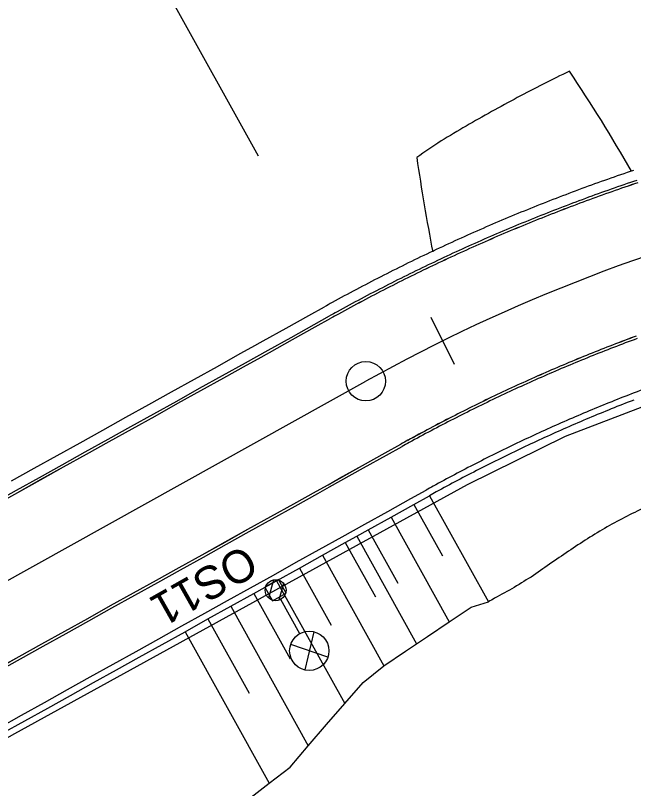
# Model space of a CAD drawing. Extents: x -783978 to -783565, y -1064821 to -1064596.
# Drawn here: x -783953.66 to -783930.06, y -1064761.44 to -1064731.94 of the extents above; entities that cross this region are included whole.
import ezdxf

# ---------------------------------------------------------------- set-up
doc = ezdxf.new("R2010")
doc.units = 0
doc.layers.add('SO 01_50_01', color=7, linetype='Continuous')
doc.layers.add('SO 01_86_02', color=7, linetype='Continuous')

msp = doc.modelspace()

# ---------------------------------------------------------------- linework, layer by layer
at = {"layer": 'SO 01_50_01'}
for p, q in [((-783958.827, -1064711.34), (-783944.395, -1064737.298)), ((-783942.455, -1064743.388), (-783941.862, -1064743.058)), ((-783942.455, -1064743.388), (-783941.862, -1064743.058)), ((-783942.455, -1064743.388), (-783941.862, -1064743.058)), ((-783943.329, -1064743.874), (-783942.455, -1064743.388)), ((-783943.329, -1064743.874), (-783942.455, -1064743.388)), ((-783943.329, -1064743.874), (-783942.455, -1064743.388)), ((-783942.261, -1064743.738), (-783941.668, -1064743.408)), ((-783942.213, -1064743.824), (-783941.619, -1064743.495)), ((-783942.212, -1064743.825), (-783941.619, -1064743.495)), ((-783936.899, -1064745.255), (-783937.783, -1064743.461)), ((-783944.203, -1064744.36), (-783943.329, -1064743.874)), ((-783944.203, -1064744.36), (-783943.329, -1064743.874)), ((-783944.203, -1064744.36), (-783943.329, -1064743.874)), ((-783943.135, -1064744.224), (-783942.261, -1064743.738)), ((-783943.087, -1064744.31), (-783942.213, -1064743.824)), ((-783943.086, -1064744.311), (-783942.212, -1064743.825)), ((-783944.009, -1064744.71), (-783943.135, -1064744.224)), ((-783944.64, -1064744.603), (-783944.203, -1064744.36)), ((-783944.64, -1064744.603), (-783944.203, -1064744.36)), ((-783944.64, -1064744.603), (-783944.203, -1064744.36)), ((-783943.961, -1064744.796), (-783943.087, -1064744.31)), ((-783943.96, -1064744.797), (-783943.086, -1064744.311)), ((-783945.951, -1064745.332), (-783945.077, -1064744.846)), ((-783945.951, -1064745.332), (-783945.077, -1064744.846)), ((-783945.951, -1064745.332), (-783945.077, -1064744.846)), ((-783945.077, -1064744.846), (-783944.64, -1064744.603)), ((-783945.077, -1064744.846), (-783944.64, -1064744.603)), ((-783945.077, -1064744.846), (-783944.64, -1064744.603)), ((-783944.446, -1064744.953), (-783944.009, -1064744.71)), ((-783944.398, -1064745.039), (-783943.961, -1064744.796)), ((-783944.397, -1064745.04), (-783943.96, -1064744.797)), ((-783944.883, -1064745.196), (-783944.446, -1064744.953)), ((-783944.835, -1064745.282), (-783944.398, -1064745.039)), ((-783944.834, -1064745.283), (-783944.397, -1064745.04)), ((-783946.825, -1064745.818), (-783945.951, -1064745.332)), ((-783946.825, -1064745.818), (-783945.951, -1064745.332)), ((-783946.825, -1064745.818), (-783945.951, -1064745.332)), ((-783945.757, -1064745.682), (-783944.883, -1064745.196)), ((-783945.709, -1064745.768), (-783944.835, -1064745.282)), ((-783945.708, -1064745.769), (-783944.834, -1064745.283)), ((-783946.631, -1064746.167), (-783945.757, -1064745.682)), ((-783972.341, -1064763.721), (-783940.283, -1064745.899)), ((-783947.699, -1064746.304), (-783946.825, -1064745.818)), ((-783947.699, -1064746.304), (-783946.825, -1064745.818)), ((-783947.699, -1064746.304), (-783946.825, -1064745.818)), ((-783946.583, -1064746.254), (-783945.709, -1064745.768)), ((-783946.582, -1064746.255), (-783945.708, -1064745.769)), ((-783948.573, -1064746.79), (-783947.699, -1064746.304)), ((-783948.573, -1064746.79), (-783947.699, -1064746.304)), ((-783948.573, -1064746.79), (-783947.699, -1064746.304)), ((-783947.505, -1064746.653), (-783946.631, -1064746.167)), ((-783947.457, -1064746.74), (-783946.583, -1064746.254)), ((-783947.457, -1064746.741), (-783946.582, -1064746.255)), ((-783949.447, -1064747.276), (-783948.573, -1064746.79)), ((-783949.447, -1064747.276), (-783948.573, -1064746.79)), ((-783949.447, -1064747.276), (-783948.573, -1064746.79)), ((-783948.379, -1064747.139), (-783947.505, -1064746.653)), ((-783948.331, -1064747.226), (-783947.457, -1064746.74)), ((-783948.331, -1064747.227), (-783947.457, -1064746.741)), ((-783949.253, -1064747.625), (-783948.379, -1064747.139)), ((-783950.321, -1064747.761), (-783949.447, -1064747.276)), ((-783950.321, -1064747.761), (-783949.447, -1064747.276)), ((-783950.321, -1064747.761), (-783949.447, -1064747.276)), ((-783949.205, -1064747.712), (-783948.331, -1064747.226)), ((-783949.205, -1064747.713), (-783948.331, -1064747.227)), ((-783951.196, -1064748.247), (-783950.321, -1064747.761)), ((-783951.196, -1064748.247), (-783950.321, -1064747.761)), ((-783951.196, -1064748.247), (-783950.321, -1064747.761)), ((-783950.127, -1064748.111), (-783949.253, -1064747.625)), ((-783950.079, -1064748.198), (-783949.205, -1064747.712)), ((-783950.079, -1064748.198), (-783949.205, -1064747.713)), ((-783952.07, -1064748.733), (-783951.196, -1064748.247)), ((-783952.07, -1064748.733), (-783951.196, -1064748.247)), ((-783952.07, -1064748.733), (-783951.196, -1064748.247)), ((-783951.001, -1064748.597), (-783950.127, -1064748.111)), ((-783950.953, -1064748.684), (-783950.079, -1064748.198)), ((-783950.953, -1064748.684), (-783950.079, -1064748.198)), ((-783939.54, -1064748.632), (-783938.947, -1064748.302)), ((-783939.539, -1064748.633), (-783938.946, -1064748.303)), ((-783939.491, -1064748.72), (-783938.898, -1064748.39)), ((-783951.875, -1064749.083), (-783951.001, -1064748.597)), ((-783951.827, -1064749.169), (-783950.953, -1064748.684)), ((-783951.827, -1064749.17), (-783950.953, -1064748.684)), ((-783940.414, -1064749.118), (-783939.54, -1064748.632)), ((-783940.413, -1064749.119), (-783939.539, -1064748.633)), ((-783952.944, -1064749.219), (-783952.07, -1064748.733)), ((-783952.944, -1064749.219), (-783952.07, -1064748.733)), ((-783952.944, -1064749.219), (-783952.07, -1064748.733)), ((-783940.365, -1064749.206), (-783939.491, -1064748.72)), ((-783953.818, -1064749.705), (-783952.944, -1064749.219)), ((-783953.818, -1064749.705), (-783952.944, -1064749.219)), ((-783953.818, -1064749.705), (-783952.944, -1064749.219)), ((-783952.749, -1064749.569), (-783951.875, -1064749.083)), ((-783952.701, -1064749.655), (-783951.827, -1064749.169)), ((-783952.701, -1064749.656), (-783951.827, -1064749.17)), ((-783941.288, -1064749.604), (-783940.414, -1064749.118)), ((-783941.287, -1064749.605), (-783940.413, -1064749.119)), ((-783941.239, -1064749.692), (-783940.365, -1064749.206)), ((-783953.623, -1064750.055), (-783952.749, -1064749.569)), ((-783953.575, -1064750.141), (-783952.701, -1064749.655)), ((-783953.575, -1064750.142), (-783952.701, -1064749.656)), ((-783942.162, -1064750.09), (-783941.725, -1064749.847)), ((-783942.162, -1064750.091), (-783941.725, -1064749.848)), ((-783941.725, -1064749.847), (-783941.288, -1064749.604)), ((-783941.725, -1064749.848), (-783941.287, -1064749.605)), ((-783941.676, -1064749.935), (-783941.239, -1064749.692)), ((-783954.497, -1064750.541), (-783953.623, -1064750.055)), ((-783954.449, -1064750.627), (-783953.575, -1064750.141)), ((-783954.449, -1064750.628), (-783953.575, -1064750.142)), ((-783943.036, -1064750.576), (-783942.162, -1064750.09)), ((-783943.036, -1064750.577), (-783942.162, -1064750.091)), ((-783942.113, -1064750.178), (-783941.676, -1064749.935)), ((-783938.568, -1064750.38), (-783937.975, -1064750.051)), ((-783942.987, -1064750.663), (-783942.113, -1064750.178)), ((-783939.442, -1064750.866), (-783938.568, -1064750.38)), ((-783938.447, -1064750.599), (-783937.853, -1064750.269)), ((-783938.447, -1064750.599), (-783937.853, -1064750.269)), ((-783938.447, -1064750.599), (-783937.853, -1064750.269)), ((-783937.853, -1064750.269), (-783935.603, -1064754.316)), ((-783943.91, -1064751.062), (-783943.036, -1064750.576)), ((-783943.91, -1064751.063), (-783943.036, -1064750.577)), ((-783943.861, -1064751.149), (-783942.987, -1064750.663)), ((-783939.321, -1064751.085), (-783938.447, -1064750.599)), ((-783939.321, -1064751.085), (-783938.447, -1064750.599)), ((-783939.321, -1064751.085), (-783938.447, -1064750.599)), ((-783938.447, -1064750.599), (-783937.356, -1064752.562)), ((-783940.316, -1064751.352), (-783939.442, -1064750.866)), ((-783944.784, -1064751.548), (-783943.91, -1064751.062)), ((-783944.784, -1064751.549), (-783943.91, -1064751.063)), ((-783944.735, -1064751.635), (-783943.861, -1064751.149)), ((-783940.753, -1064751.595), (-783940.316, -1064751.352)), ((-783940.195, -1064751.571), (-783939.321, -1064751.085)), ((-783940.195, -1064751.571), (-783939.321, -1064751.085)), ((-783940.195, -1064751.571), (-783939.321, -1064751.085)), ((-783939.321, -1064751.085), (-783937.097, -1064755.085)), ((-783945.658, -1064752.034), (-783944.784, -1064751.548)), ((-783945.658, -1064752.035), (-783944.784, -1064751.549)), ((-783945.609, -1064752.121), (-783944.735, -1064751.635)), ((-783941.19, -1064751.838), (-783940.753, -1064751.595)), ((-783940.632, -1064751.814), (-783940.195, -1064751.571)), ((-783940.632, -1064751.814), (-783940.195, -1064751.571)), ((-783940.632, -1064751.814), (-783940.195, -1064751.571)), ((-783940.195, -1064751.571), (-783939.062, -1064753.607)), ((-783942.064, -1064752.324), (-783941.19, -1064751.838)), ((-783941.069, -1064752.057), (-783940.632, -1064751.814)), ((-783941.069, -1064752.057), (-783940.632, -1064751.814)), ((-783941.069, -1064752.057), (-783940.632, -1064751.814)), ((-783940.632, -1064751.814), (-783938.347, -1064755.923)), ((-783946.532, -1064752.52), (-783945.658, -1064752.034)), ((-783946.532, -1064752.521), (-783945.658, -1064752.035)), ((-783946.483, -1064752.607), (-783945.609, -1064752.121)), ((-783941.943, -1064752.543), (-783941.069, -1064752.057)), ((-783941.943, -1064752.543), (-783941.069, -1064752.057)), ((-783941.943, -1064752.543), (-783941.069, -1064752.057)), ((-783941.069, -1064752.057), (-783939.917, -1064754.13)), ((-783947.406, -1064753.006), (-783946.532, -1064752.52)), ((-783947.406, -1064753.006), (-783946.532, -1064752.521)), ((-783942.938, -1064752.81), (-783942.064, -1064752.324)), ((-783947.357, -1064753.093), (-783946.483, -1064752.607)), ((-783943.812, -1064753.296), (-783942.938, -1064752.81)), ((-783942.817, -1064753.028), (-783941.943, -1064752.543)), ((-783942.817, -1064753.028), (-783941.943, -1064752.543)), ((-783942.817, -1064753.028), (-783941.943, -1064752.543)), ((-783941.943, -1064752.543), (-783939.597, -1064756.763)), ((-783948.28, -1064753.492), (-783947.406, -1064753.006)), ((-783948.28, -1064753.491), (-783947.406, -1064753.006)), ((-783948.231, -1064753.579), (-783947.357, -1064753.093)), ((-783943.691, -1064753.514), (-783942.817, -1064753.028)), ((-783943.691, -1064753.514), (-783942.817, -1064753.028)), ((-783943.691, -1064753.514), (-783942.817, -1064753.028)), ((-783942.817, -1064753.028), (-783941.602, -1064755.213)), ((-783944.686, -1064753.782), (-783943.812, -1064753.296)), ((-783949.154, -1064753.977), (-783948.28, -1064753.491)), ((-783949.154, -1064753.978), (-783948.28, -1064753.492)), ((-783949.106, -1064754.065), (-783948.231, -1064753.579)), ((-783944.565, -1064754), (-783943.691, -1064753.514)), ((-783944.565, -1064754), (-783943.691, -1064753.514)), ((-783944.565, -1064754), (-783943.691, -1064753.514)), ((-783943.691, -1064753.514), (-783941.088, -1064758.196)), ((-783950.028, -1064754.463), (-783949.154, -1064753.977)), ((-783950.028, -1064754.464), (-783949.154, -1064753.978)), ((-783945.56, -1064754.268), (-783944.686, -1064753.782)), ((-783945.439, -1064754.486), (-783944.565, -1064754)), ((-783945.439, -1064754.486), (-783944.565, -1064754)), ((-783945.439, -1064754.486), (-783944.565, -1064754)), ((-783944.565, -1064754), (-783943.177, -1064756.498)), ((-783949.98, -1064754.551), (-783949.106, -1064754.065)), ((-783946.434, -1064754.754), (-783945.56, -1064754.268)), ((-783950.902, -1064754.949), (-783950.028, -1064754.463)), ((-783950.902, -1064754.95), (-783950.028, -1064754.464)), ((-783950.854, -1064755.037), (-783949.98, -1064754.551)), ((-783946.313, -1064754.972), (-783945.439, -1064754.486)), ((-783946.313, -1064754.972), (-783945.439, -1064754.486)), ((-783946.313, -1064754.972), (-783945.439, -1064754.486)), ((-783945.439, -1064754.486), (-783942.48, -1064759.808)), ((-783937.097, -1064755.085), (-783936.264, -1064754.525)), ((-783936.264, -1064754.525), (-783935.603, -1064754.316)), ((-783947.308, -1064755.239), (-783946.434, -1064754.754)), ((-783951.776, -1064755.435), (-783950.902, -1064754.949)), ((-783951.776, -1064755.436), (-783950.902, -1064754.95)), ((-783951.728, -1064755.522), (-783950.854, -1064755.037)), ((-783947.187, -1064755.458), (-783946.313, -1064754.972)), ((-783947.187, -1064755.458), (-783946.313, -1064754.972)), ((-783947.187, -1064755.458), (-783946.313, -1064754.972)), ((-783946.313, -1064754.972), (-783944.741, -1064757.8)), ((-783937.93, -1064755.644), (-783937.097, -1064755.085)), ((-783952.65, -1064755.921), (-783951.776, -1064755.435)), ((-783952.65, -1064755.922), (-783951.776, -1064755.436)), ((-783948.182, -1064755.725), (-783947.308, -1064755.239)), ((-783948.061, -1064755.944), (-783947.187, -1064755.458)), ((-783948.061, -1064755.944), (-783947.187, -1064755.458)), ((-783948.061, -1064755.944), (-783947.187, -1064755.458)), ((-783947.187, -1064755.458), (-783943.971, -1064761.243)), ((-783952.602, -1064756.008), (-783951.728, -1064755.522)), ((-783949.056, -1064756.211), (-783948.182, -1064755.725)), ((-783938.347, -1064755.923), (-783937.93, -1064755.644)), ((-783953.524, -1064756.407), (-783952.65, -1064755.921)), ((-783953.524, -1064756.408), (-783952.65, -1064755.922)), ((-783953.476, -1064756.494), (-783952.602, -1064756.008)), ((-783948.935, -1064756.43), (-783948.061, -1064755.944)), ((-783948.935, -1064756.43), (-783948.061, -1064755.944)), ((-783948.935, -1064756.43), (-783948.061, -1064755.944)), ((-783938.764, -1064756.203), (-783938.347, -1064755.923)), ((-783949.93, -1064756.697), (-783949.056, -1064756.211)), ((-783939.597, -1064756.763), (-783938.764, -1064756.203)), ((-783954.398, -1064756.893), (-783953.524, -1064756.407)), ((-783954.398, -1064756.894), (-783953.524, -1064756.408)), ((-783954.35, -1064756.98), (-783953.476, -1064756.494)), ((-783949.809, -1064756.916), (-783948.935, -1064756.43)), ((-783949.809, -1064756.916), (-783948.935, -1064756.43)), ((-783949.809, -1064756.916), (-783948.935, -1064756.43)), ((-783950.804, -1064757.183), (-783949.93, -1064756.697)), ((-783950.683, -1064757.402), (-783949.809, -1064756.916)), ((-783950.683, -1064757.402), (-783949.809, -1064756.916)), ((-783950.683, -1064757.402), (-783949.809, -1064756.916)), ((-783940.387, -1064757.398), (-783939.597, -1064756.763)), ((-783951.678, -1064757.669), (-783950.804, -1064757.183)), ((-783951.557, -1064757.888), (-783950.683, -1064757.402)), ((-783951.557, -1064757.888), (-783950.683, -1064757.402)), ((-783951.557, -1064757.888), (-783950.683, -1064757.402)), ((-783941.088, -1064758.196), (-783940.387, -1064757.398)), ((-783952.552, -1064758.155), (-783951.678, -1064757.669)), ((-783952.431, -1064758.373), (-783951.557, -1064757.888)), ((-783952.431, -1064758.373), (-783951.557, -1064757.888)), ((-783952.431, -1064758.373), (-783951.557, -1064757.888)), ((-783953.426, -1064758.641), (-783952.552, -1064758.155)), ((-783953.305, -1064758.859), (-783952.431, -1064758.373)), ((-783953.305, -1064758.859), (-783952.431, -1064758.373)), ((-783953.305, -1064758.859), (-783952.431, -1064758.373)), ((-783941.788, -1064758.995), (-783941.088, -1064758.196)), ((-783954.3, -1064759.127), (-783953.426, -1064758.641)), ((-783954.179, -1064759.345), (-783953.305, -1064758.859)), ((-783954.179, -1064759.345), (-783953.305, -1064758.859)), ((-783954.179, -1064759.345), (-783953.305, -1064758.859)), ((-783942.48, -1064759.808), (-783941.788, -1064758.995)), ((-783943.169, -1064760.627), (-783942.48, -1064759.808)), ((-783943.971, -1064761.243), (-783943.169, -1064760.627)), ((-783944.772, -1064761.859), (-783943.971, -1064761.243))]:
    msp.add_line(p, q, dxfattribs=at)
msp.add_circle((-783940.283, -1064745.899), 0.75, dxfattribs=at)
for centre, radius, start, end in [((-783899.876, -1064801.18), 74.628, 115.92572, 116.78575), ((-783990.619, -1064772.828), 69.857, 30.02146, 33.70531), ((-783899.709, -1064800.952), 74.501, 116.97966, 117.84), ((-783899.487, -1064800.686), 74.369, 118.08659, 118.94737), ((-783899.252, -1064800.4), 74.233, 119.21346, 120.07472), ((-783899.122, -1064800.161), 74.092, 120.25393, 121.11552), ((-783896.278, -1064798.182), 73.948, 123.79552, 124.66308), ((-783907.727, -1064804.458), 67, 86.89792, 119.07174), ((-783865.342, -1064726.823), 73.751, 188.2134, 191.05213), ((-783907.727, -1064804.458), 70.25, 108.53542, 109.39058), ((-783907.727, -1064804.458), 70.25, 108.53542, 109.39058), ((-783907.727, -1064804.458), 70.25, 108.53542, 109.39058), ((-783907.727, -1064804.458), 70.25, 109.39058, 110.24574), ((-783907.727, -1064804.458), 70.25, 109.39058, 110.24574), ((-783907.727, -1064804.458), 70.25, 109.39058, 110.24574), ((-783907.727, -1064804.458), 69.85, 108.53542, 109.39058), ((-783907.727, -1064804.458), 69.751, 108.53542, 109.39058), ((-783907.727, -1064804.458), 69.75, 108.53542, 109.39058), ((-783907.727, -1064804.458), 70.25, 110.24574, 111.1009), ((-783907.727, -1064804.458), 70.25, 110.24574, 111.1009), ((-783907.727, -1064804.458), 70.25, 110.24574, 111.1009), ((-783907.727, -1064804.458), 69.85, 109.39058, 110.24574), ((-783907.727, -1064804.458), 69.751, 109.39058, 110.24574), ((-783907.727, -1064804.458), 69.75, 109.39058, 110.24574), ((-783907.727, -1064804.458), 70.25, 111.1009, 111.95606), ((-783907.727, -1064804.458), 70.25, 111.1009, 111.95606), ((-783907.727, -1064804.458), 70.25, 111.1009, 111.95606), ((-783907.727, -1064804.458), 69.85, 110.24574, 111.1009), ((-783907.727, -1064804.458), 69.751, 110.24574, 111.1009), ((-783907.727, -1064804.458), 69.75, 110.24574, 111.1009), ((-783907.727, -1064804.458), 70.25, 111.95606, 112.81123), ((-783907.727, -1064804.458), 70.25, 111.95606, 112.81123), ((-783907.727, -1064804.458), 70.25, 111.95606, 112.81123), ((-783907.727, -1064804.458), 69.85, 111.1009, 111.95606), ((-783907.727, -1064804.458), 69.751, 111.1009, 111.95606), ((-783907.727, -1064804.458), 69.75, 111.1009, 111.95606), ((-783907.727, -1064804.458), 70.25, 112.81123, 113.66639), ((-783907.727, -1064804.458), 70.25, 112.81123, 113.66639), ((-783907.727, -1064804.458), 70.25, 112.81123, 113.66639), ((-783907.727, -1064804.458), 69.85, 111.95606, 112.81123), ((-783907.727, -1064804.458), 69.751, 111.95606, 112.81123), ((-783907.727, -1064804.458), 69.75, 111.95606, 112.81123), ((-783907.727, -1064804.458), 70.25, 113.66639, 114.52155), ((-783907.727, -1064804.458), 70.25, 113.66639, 114.52155), ((-783907.727, -1064804.458), 70.25, 113.66639, 114.52155), ((-783907.727, -1064804.458), 69.85, 112.81123, 113.66639), ((-783907.727, -1064804.458), 69.751, 112.81123, 113.66639), ((-783907.727, -1064804.458), 69.75, 112.81123, 113.66639), ((-783907.727, -1064804.458), 70.25, 114.52155, 115.37671), ((-783907.727, -1064804.458), 70.25, 114.52155, 115.37671), ((-783907.727, -1064804.458), 70.25, 114.52155, 115.37671), ((-783907.727, -1064804.458), 69.85, 113.66639, 114.52155), ((-783907.727, -1064804.458), 69.751, 113.66639, 114.52155), ((-783907.727, -1064804.458), 69.75, 113.66639, 114.52155), ((-783907.727, -1064804.458), 70.25, 115.37671, 116.23187), ((-783907.727, -1064804.458), 70.25, 115.37671, 116.23187), ((-783907.727, -1064804.458), 70.25, 115.37671, 116.23187), ((-783907.727, -1064804.458), 69.85, 114.52155, 115.37671), ((-783907.727, -1064804.458), 69.751, 114.52155, 115.37671), ((-783907.727, -1064804.458), 69.75, 114.52155, 115.37671), ((-783907.727, -1064804.458), 70.25, 116.23187, 117.08703), ((-783907.727, -1064804.458), 70.25, 116.23187, 117.08703), ((-783907.727, -1064804.458), 70.25, 116.23187, 117.08703), ((-783907.727, -1064804.458), 69.85, 115.37671, 116.23187), ((-783907.727, -1064804.458), 69.751, 115.37671, 116.23187), ((-783907.727, -1064804.458), 69.75, 115.37671, 116.23187), ((-783907.727, -1064804.458), 69.85, 116.23187, 117.08703), ((-783907.727, -1064804.458), 69.751, 116.23187, 117.08703), ((-783907.727, -1064804.458), 69.75, 116.23187, 117.08703), ((-783907.727, -1064804.458), 70.25, 117.08703, 117.94219), ((-783907.727, -1064804.458), 70.25, 117.08703, 117.94219), ((-783907.727, -1064804.458), 70.25, 117.08703, 117.94219), ((-783907.727, -1064804.458), 70.25, 117.94219, 118.79735), ((-783907.727, -1064804.458), 70.25, 117.94219, 118.79735), ((-783907.727, -1064804.458), 70.25, 117.94219, 118.79735), ((-783907.727, -1064804.458), 69.85, 117.08703, 117.94219), ((-783907.727, -1064804.458), 69.751, 117.08703, 117.94219), ((-783907.727, -1064804.458), 69.75, 117.08703, 117.94219), ((-783907.727, -1064804.458), 69.85, 117.94219, 118.79735), ((-783907.727, -1064804.458), 70.25, 118.79735, 119.07185), ((-783907.727, -1064804.458), 70.25, 118.79735, 119.07185), ((-783907.727, -1064804.458), 70.25, 118.79735, 119.07185), ((-783907.727, -1064804.458), 69.751, 117.94219, 118.79735), ((-783907.727, -1064804.458), 69.75, 117.94219, 118.79735), ((-783924.624, -1064773.892), 34.925, 118.6601, 119.2091), ((-783924.6, -1064773.935), 34.875, 118.6601, 119.2091), ((-783907.727, -1064804.458), 69.75, 118.79735, 119.07185), ((-783907.727, -1064804.458), 64.25, 110.24574, 111.1009), ((-783907.727, -1064804.458), 64.249, 110.24574, 111.1009), ((-783907.727, -1064804.458), 64.15, 110.24574, 111.1009), ((-783907.727, -1064804.458), 64.25, 111.1009, 111.95606), ((-783907.727, -1064804.458), 64.249, 111.1009, 111.95606), ((-783907.727, -1064804.458), 64.15, 111.1009, 111.95606), ((-783907.727, -1064804.458), 64.25, 111.95606, 112.81123), ((-783907.727, -1064804.458), 64.249, 111.95606, 112.81123), ((-783907.727, -1064804.458), 64.15, 111.95606, 112.81123), ((-783907.727, -1064804.458), 64.25, 112.81123, 113.66639), ((-783907.727, -1064804.458), 64.249, 112.81123, 113.66639), ((-783907.727, -1064804.458), 64.15, 112.81123, 113.66639), ((-783907.727, -1064804.458), 64.25, 113.66639, 114.52155), ((-783907.727, -1064804.458), 64.249, 113.66639, 114.52155), ((-783907.727, -1064804.458), 64.15, 113.66639, 114.52155), ((-783907.727, -1064804.458), 64.25, 114.52155, 115.37671), ((-783907.727, -1064804.458), 64.249, 114.52155, 115.37671), ((-783907.727, -1064804.458), 64.15, 114.52155, 115.37671), ((-783907.727, -1064804.458), 62.25, 110.24574, 111.1009), ((-783907.727, -1064804.458), 64.25, 115.37671, 116.23187), ((-783907.727, -1064804.458), 64.249, 115.37671, 116.23187), ((-783907.727, -1064804.458), 64.15, 115.37671, 116.23187), ((-783907.727, -1064804.458), 62.25, 111.1009, 111.95606), ((-783907.727, -1064804.458), 62, 111.1009, 111.95606), ((-783907.727, -1064804.458), 62, 111.1009, 111.95606), ((-783907.727, -1064804.458), 62, 111.1009, 111.95606), ((-783907.727, -1064804.458), 64.25, 116.23187, 117.08703), ((-783907.727, -1064804.458), 64.249, 116.23187, 117.08703), ((-783907.727, -1064804.458), 64.15, 116.23187, 117.08703), ((-783907.727, -1064804.458), 62.25, 111.95606, 112.81123), ((-783907.727, -1064804.458), 62.25, 112.81123, 113.66639), ((-783907.727, -1064804.458), 62, 111.95606, 112.81123), ((-783907.727, -1064804.458), 62, 111.95606, 112.81123), ((-783907.727, -1064804.458), 62, 111.95606, 112.81123), ((-783907.727, -1064804.458), 64.25, 117.08703, 117.94219), ((-783907.727, -1064804.458), 64.249, 117.08703, 117.94219), ((-783907.727, -1064804.458), 64.15, 117.08703, 117.94219), ((-783907.727, -1064804.458), 62.25, 113.66639, 114.52155), ((-783907.727, -1064804.458), 62, 112.81123, 113.66639), ((-783907.727, -1064804.458), 62, 112.81123, 113.66639), ((-783907.727, -1064804.458), 62, 112.81123, 113.66639), ((-783907.727, -1064804.458), 64.25, 117.94219, 118.79735), ((-783907.727, -1064804.458), 64.249, 117.94219, 118.79735), ((-783907.727, -1064804.458), 64.15, 117.94219, 118.79735), ((-783907.727, -1064804.458), 62, 113.66639, 114.52155), ((-783907.727, -1064804.458), 62, 113.66639, 114.52155), ((-783907.727, -1064804.458), 62, 113.66639, 114.52155), ((-783907.727, -1064804.458), 62.25, 114.52155, 115.37671), ((-783907.727, -1064804.458), 62, 114.52155, 115.37671), ((-783907.727, -1064804.458), 62, 114.52155, 115.37671), ((-783907.727, -1064804.458), 62, 114.52155, 115.37671), ((-783907.727, -1064804.458), 64.25, 118.79735, 119.07186), ((-783923.269, -1064776.343), 32.125, 118.6601, 119.2091), ((-783923.245, -1064776.386), 32.075, 118.6601, 119.2091), ((-783907.727, -1064804.458), 62.25, 115.37671, 116.23187), ((-783907.727, -1064804.458), 62.25, 116.23187, 117.08703), ((-783907.727, -1064804.458), 62, 115.37671, 116.23187), ((-783907.727, -1064804.458), 62, 115.37671, 116.23187), ((-783907.727, -1064804.458), 62, 115.37671, 116.23187), ((-783907.727, -1064804.458), 62, 116.23187, 117.08703), ((-783907.727, -1064804.458), 62, 116.23187, 117.08703), ((-783907.727, -1064804.458), 62, 116.23187, 117.08703), ((-783907.727, -1064804.458), 62.25, 117.08703, 117.94219), ((-783907.727, -1064804.458), 62, 117.08703, 117.94219), ((-783907.727, -1064804.458), 62, 117.08703, 117.94219), ((-783907.727, -1064804.458), 62, 117.08703, 117.94219), ((-783907.727, -1064804.458), 62.25, 117.94219, 118.79735), ((-783907.727, -1064804.458), 62, 117.94219, 118.79735), ((-783907.727, -1064804.458), 62, 117.94219, 118.79735), ((-783907.727, -1064804.458), 62, 117.94219, 118.79735), ((-783922.786, -1064777.218), 31.125, 118.6601, 119.2091), ((-783907.727, -1064804.458), 62, 118.79735, 119.07187), ((-783907.727, -1064804.458), 62, 118.79735, 119.07187), ((-783907.727, -1064804.458), 62, 118.79735, 119.07187), ((-783903.892, -1064802.748), 58.054, 116.10066, 116.9576), ((-783903.697, -1064802.578), 57.992, 117.20634, 118.06353), ((-783901.565, -1064801.306), 57.925, 120.51659, 121.37714), ((-783900.468, -1064800.496), 57.821, 122.72299, 123.58606), ((-783900.414, -1064800.311), 57.697, 123.73237, 124.59576), ((-783900.365, -1064800.123), 57.571, 124.74204, 125.60577), ((-783904.056, -1064802.407), 57.442, 121.28213, 122.13912), ((-783907.322, -1064804.241), 57.379, 118.40057, 119.25571), ((-783907.226, -1064804.179), 57.372, 119.37041, 119.64494)]:
    msp.add_arc(centre, radius, start, end, dxfattribs=at)
at = {"layer": 'SO 01_86_02'}
for p, q in [((-783943.806, -1064753.486), (-783944, -1064754.166)), ((-783943.427, -1064753.615), (-783943.609, -1064754.253)), ((-783942.805, -1064755.535), (-783943.534, -1064754.224)), ((-783942.274, -1064755.46), (-783942.609, -1064756.919)), ((-783941.733, -1064756.432), (-783943.15, -1064755.946))]:
    msp.add_line(p, q, dxfattribs=at)
msp.add_lwpolyline([(-783878.171, -1064745.018), (-783878.186, -1064744.275), (-783880.673, -1064744.123), (-783888.395, -1064743.656), (-783896.118, -1064743.19), (-783902.642, -1064742.943), (-783906.922, -1064742.781), (-783908.615, -1064742.797), (-783910.308, -1064742.813), (-783914.084, -1064743.083), (-783917.528, -1064743.556), (-783921.591, -1064744.335), (-783924.038, -1064744.952), (-783925.195, -1064745.304), (-783928.174, -1064746.293), (-783932.665, -1064748.008), (-783936.408, -1064749.851), (-783943.728, -1064753.874), (-783953.702, -1064759.355), (-783962.96, -1064764.568)], dxfattribs=at)
msp.add_lwpolyline([(-783943.842, -1064754.283), (-783943.32, -1064753.988), (-783943.615, -1064753.465), (-783944.137, -1064753.761)], close=True, dxfattribs=at)
for centre, radius in [((-783943.728, -1064753.874), 0.4), ((-783942.442, -1064756.189), 0.749)]:
    msp.add_circle(centre, radius, dxfattribs=at)

# ---------------------------------------------------------------- texts
msp.add_text('OS11', height=1.25, rotation=209.4671, dxfattribs=at).set_placement((-783944.9, -1064752.108))

doc.saveas('drawing.dxf')
